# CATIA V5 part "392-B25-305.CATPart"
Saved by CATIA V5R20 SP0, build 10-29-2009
Part number: 392-B25-305
Definition: NONE
Nomenclature: 392-B25-305
Source: Unknown
Description: 392-B25-305
Bounding box of the stored display mesh (mm): x 0 to 305, y -12.352 to 12.352, z -12.25 to 12.064
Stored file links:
  C:\Users\Utente\Desktop\IO LAVORO\3D X SITO CF\X SITO\3D files 392B\392-B25-305.CATPart
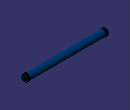
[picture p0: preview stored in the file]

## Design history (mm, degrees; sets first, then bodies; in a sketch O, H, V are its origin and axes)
Body1 "392-B25-305" (main body)
  Solid1: solid without history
